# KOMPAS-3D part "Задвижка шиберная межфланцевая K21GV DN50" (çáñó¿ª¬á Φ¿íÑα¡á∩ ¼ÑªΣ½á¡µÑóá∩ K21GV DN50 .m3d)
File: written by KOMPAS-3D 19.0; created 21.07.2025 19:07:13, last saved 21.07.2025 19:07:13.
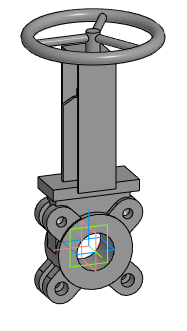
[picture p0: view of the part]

Document properties: Автор: Евгений; Полное имя файла: E:\Dendor Работа Сачек\3D для проектировщиков\2.3 Тип K21GV. Задвижка шиберная межфланцевая\stp_Задвижка шиберная K21GV DN50-400 с маховиком\Задвижка шиберная межфланцевая K21GV DN50 .m3d

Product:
- Part/product: Задвижка шиберная межфланцевая K21GV DN50

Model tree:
1. Операция без истории:1  (labels: Задвижка шиберная межфланцевая K21GV DN50)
